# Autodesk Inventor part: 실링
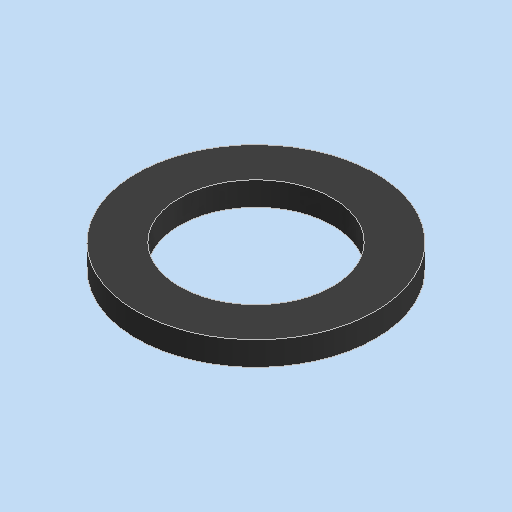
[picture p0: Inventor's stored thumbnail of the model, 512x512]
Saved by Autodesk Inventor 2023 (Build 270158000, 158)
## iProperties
Created: 2024-11
Part Number: 실링
Material: 고무
Document SubType Name: Modeling
Designer: asung
Density: 0.93 g/cm^3
Appearance: 기본값
Author: jhkim
Sending System: Autodesk Inventor 2025
Preprocessor: ST-DEVELOPER v20
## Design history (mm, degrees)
node "실링1"
node "솔리드2"
node "솔리드1"
